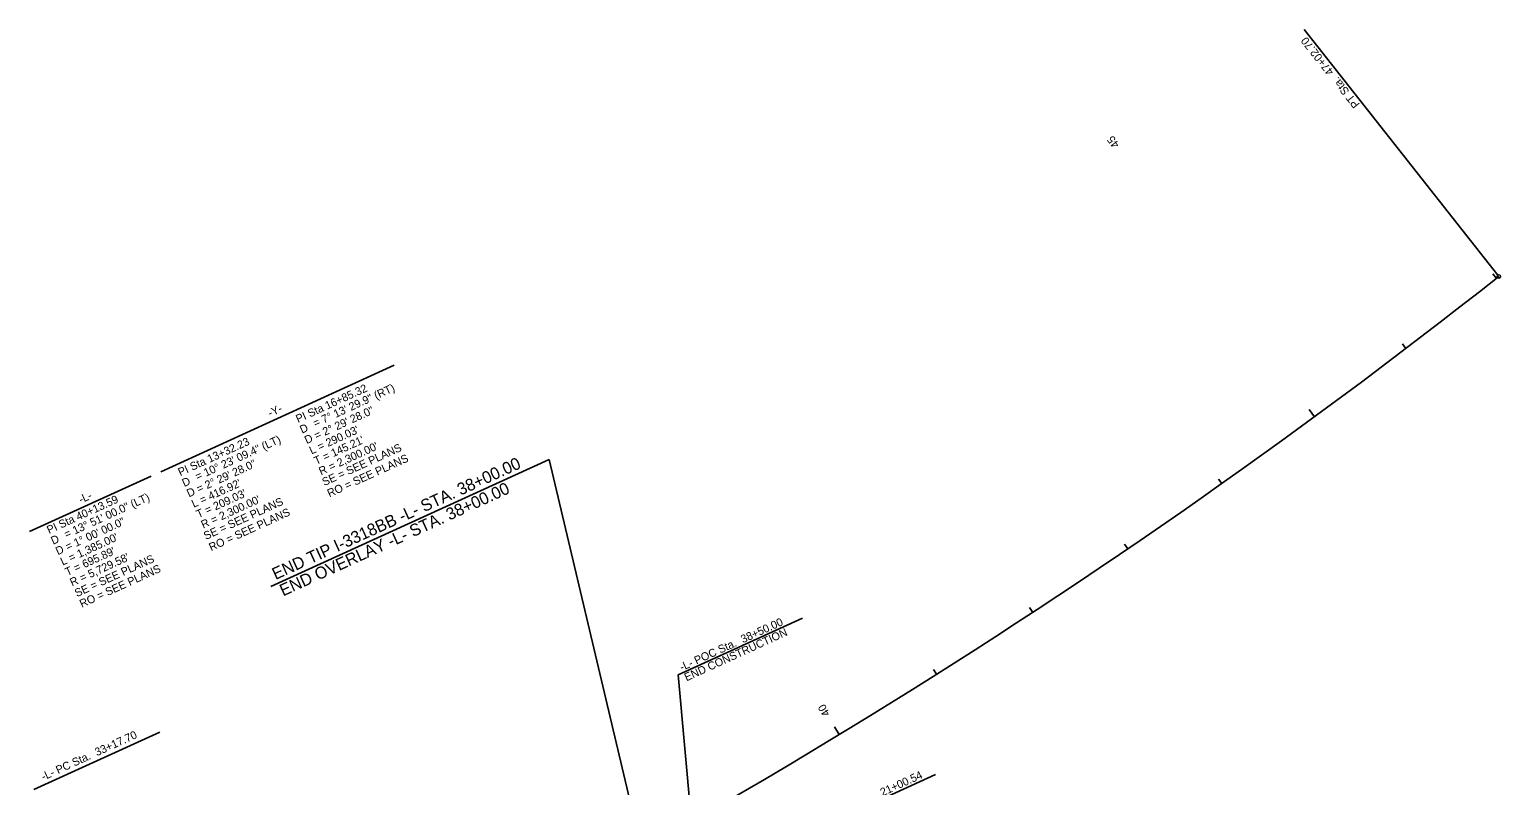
# Model space of a CAD drawing. Extents: x 2242984 to 2250974, y 661492 to 664681.
# Drawn here: x 2249688 to 2250974, y 664020 to 664681 of the extents above; entities that cross this region are included whole.
import ezdxf

# ---------------------------------------------------------------- set-up
doc = ezdxf.new("R2010")
doc.units = 0
for name, color, linetype in [('Prop Dimension', 7, 'Continuous'), ('Prop Horizontal Alignment', 7, 'Continuous'), ('Prop Horizontal Alignment Curve and Spiral Data', 7, 'Continuous'), ('Prop Horizontal Alignment Station Label', 7, 'Continuous'), ('Prop Horizontal Alignment Tick Label', 7, 'Continuous'), ('Prop Horizontal Alignment Tick Large', 7, 'Continuous'), ('Prop Horizontal Alignment Tick Small', 7, 'Continuous')]:
    doc.layers.add(name, color=color, linetype=linetype)

msp = doc.modelspace()

# ---------------------------------------------------------------- linework, layer by layer
at = {"layer": 'Prop Dimension'}
for q in [(2249898.7, 664194.3), (2250223.3, 663964)]:
    msp.add_line((2250142.2, 664305.3), q, dxfattribs=at)
at = {"layer": 'Prop Horizontal Alignment'}
msp.add_arc((2247423.4, 668962.9), 5729.6, 294.4301, 308.2801, dxfattribs=at)
at = {"layer": 'Prop Horizontal Alignment Station Label'}
for p, q in [((2250972, 664466.4), (2250802.6, 664681.1)), ((2249802.5, 664294.4), (2250006.8, 664387.5)), ((2249687.7, 664242.1), (2249794.3, 664290.7)), ((2250363.9, 664166.6), (2250255.1, 664117)), ((2250266.8, 663988.6), (2250255.1, 664117)), ((2249691.6, 664016.6), (2249801.6, 664066.8)), ((2250480.3, 664029.8), (2250384.4, 663986.1))]:
    msp.add_line(p, q, dxfattribs=at)
msp.add_circle((2250972.9, 664465.2), 1.5, dxfattribs=at)
at = {"layer": 'Prop Horizontal Alignment Tick Large'}
for p, q in [((2250811.6, 664342.5), (2250806.9, 664348.9)), ((2250396, 664064.8), (2250391.9, 664071.6))]:
    msp.add_line(p, q, dxfattribs=at)
at = {"layer": 'Prop Horizontal Alignment Tick Small'}
for p, q in [((2250970.8, 664463.5), (2250967.7, 664467.5)), ((2250891.7, 664402.3), (2250888.7, 664406.3)), ((2250730.5, 664284.1), (2250727.6, 664288.1)), ((2250648.3, 664227), (2250645.5, 664231.2)), ((2250565.2, 664171.5), (2250562.4, 664175.7)), ((2250481.1, 664117.4), (2250478.4, 664121.6))]:
    msp.add_line(p, q, dxfattribs=at)

# ---------------------------------------------------------------- texts
at = {"layer": 'Prop Dimension'}
for s, p in [('END TIP I-3318BB -L- STA. 38+00.00  ', (2249902.9, 664199.8)), ('END OVERLAY -L- STA. 38+00.00', (2249909.5, 664185.4))]:
    msp.add_text(s, height=10.5, rotation=24.4979, dxfattribs=at).set_placement(p)
at = {"layer": 'Prop Horizontal Alignment Curve and Spiral Data'}
for s, p in [('PI Sta 16+85.32', (2249922.6, 664337.1)), ('= 7%%d 13\' 29.9" (RT)', (2249937.7, 664333.3)), ('-Y-', (2249898.2, 664342.2)), ('D = 2%%d 29\' 28.0"', (2249930.2, 664318.6)), ('D', (2249926.1, 664327.7)), ("L = 290.03'", (2249934.4, 664309.5)), ('PI Sta 13+32.23', (2249819.6, 664290.5)), ('= 10%%d 23\' 09.4" (LT)', (2249834.7, 664286.7)), ("T = 145.21'", (2249938.5, 664300.4)), ("R = 2,300.00'", (2249942.7, 664291.3)), ('SE = SEE PLANS', (2249945.6, 664281.9)), ('D = 2%%d 29\' 28.0"', (2249827.2, 664272)), ('RO = SEE PLANS', (2249950.1, 664272)), ('D', (2249823.1, 664281.1)), ("L = 416.92'", (2249831.4, 664262.9)), ("T = 209.03'", (2249835.5, 664253.8)), ('PI Sta 40+13.59', (2249704.8, 664240)), ('= 13%%d 51\' 00.0" (LT)', (2249720, 664236.2)), ('-L-', (2249732.7, 664266.6)), ("R = 2,300.00'", (2249839.7, 664244.7)), ('SE = SEE PLANS', (2249842, 664234.8)), ('D = 1%%d 00\' 00.0"', (2249712.5, 664221.5)), ('RO = SEE PLANS', (2249846.6, 664224.9)), ('D', (2249708.4, 664230.6)), ("L = 1,385.00'", (2249716.7, 664212.4)), ("T = 695.89'", (2249720.8, 664203.3)), ("R = 5,729.58'", (2249725, 664194.2)), ('SE = SEE PLANS', (2249729.2, 664184.8)), ('RO = SEE PLANS', (2249733.5, 664175.5))]:
    msp.add_text(s, height=7, rotation=24.4979, dxfattribs=at).set_placement(p)
at = {"layer": 'Prop Horizontal Alignment Station Label'}
for s, rotation, p in [('PT Sta.  47+02.70', 128.2801, (2250851.6, 664615.7)), ('PT Sta.  47+02.70', 128.2801, (2250851.6, 664615.7)), ('-L- POC Sta.  38+50.00', 24.4979, (2250258.3, 664120.1)), ('END CONSTRUCTION', 24.4979, (2250262.4, 664111.2)), ('-L- PC Sta.  33+17.70', 24.4979, (2249699.9, 664024.4)), ('-Y- PT Sta.  21+00.54', 24.4979, (2250386.9, 663989.3))]:
    msp.add_text(s, height=7, rotation=rotation, dxfattribs=at).set_placement(p)
at = {"layer": 'Prop Horizontal Alignment Tick Label'}
for s, rotation, p in [('45', 126.2532, (2250641.4, 664580.5)), ('40', 121.2532, (2250388.3, 664083.2))]:
    msp.add_text(s, height=7, rotation=rotation, dxfattribs=at).set_placement(p)

doc.saveas('drawing.dxf')
